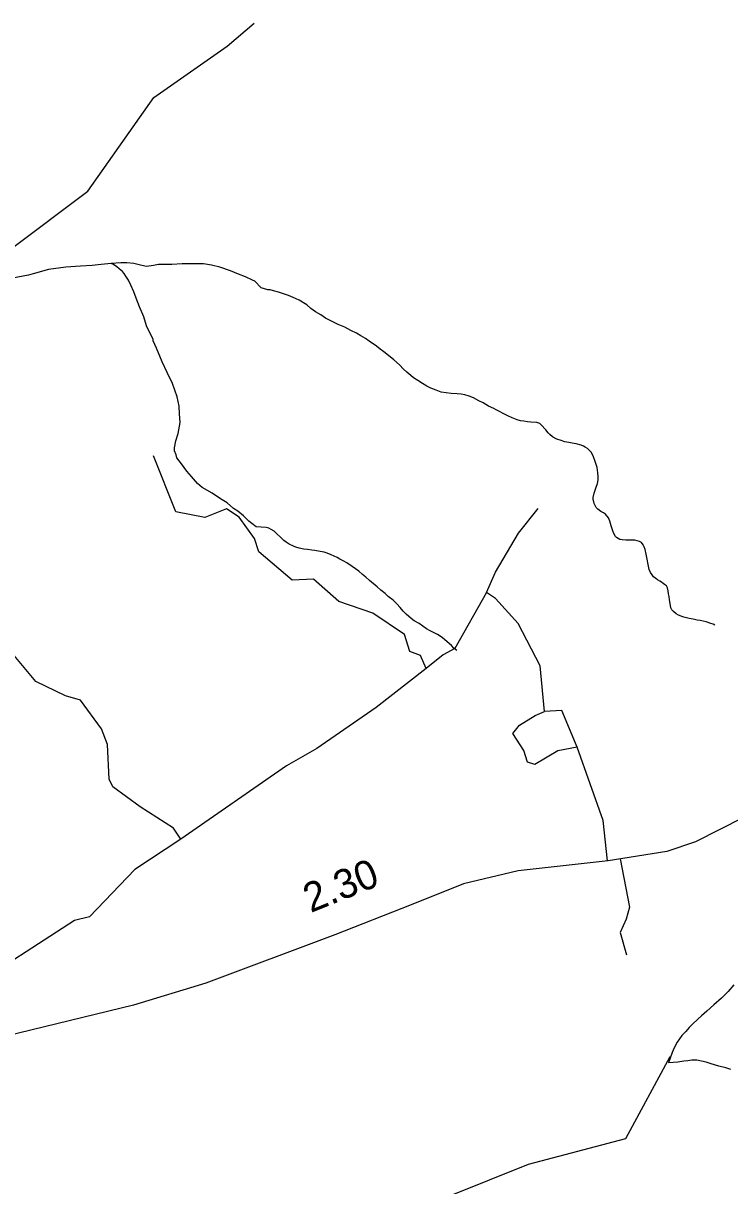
# Model space of a CAD drawing. Extents: x 2056842 to 2160602, y 826753 to 1016856.
# Drawn here: x 2109914 to 2112934, y 842001 to 846968 of the extents above; entities that cross this region are included whole.
import ezdxf

# ---------------------------------------------------------------- set-up
doc = ezdxf.new("R2010")
doc.units = 0
for name, color, linetype in [('Exist Hydrographic Creek Single Shore', 7, 'Continuous'), ('Exist Hydrographic Misc Water Feature', 7, 'Continuous'), ('Exist Road Non-System Type 51', 7, 'Continuous'), ('Exist Road Secondary Mileage Hundredths English Label', 7, 'Continuous'), ('Exist Road Secondary Type 51 Attributed', 7, 'Continuous')]:
    doc.layers.add(name, color=color, linetype=linetype)

msp = doc.modelspace()

# ---------------------------------------------------------------- linework, layer by layer
at = {"layer": 'Exist Hydrographic Creek Single Shore'}
msp.add_lwpolyline([(2108168.9, 845471), (2108304.5, 845502.1), (2109014.8, 845654.3), (2109225, 845779.8), (2109375, 845866), (2109549.9, 845924.8), (2109733, 845940.7), (2109857.9, 846000.5), (2110190.9, 846249.6), (2110472.9, 846650.6), (2110785.6, 846869.5), (2110900.7, 846967.7)], dxfattribs=at)
at = {"layer": 'Exist Hydrographic Misc Water Feature'}
for points in [[(2110290.4, 845940.5), (2110246.6, 845936.3), (2110208.8, 845932.2), (2110158.8, 845930.1), (2110096.5, 845925.7), (2110022.4, 845915.4), (2109956.6, 845897.4), (2109936.7, 845891.1), (2109868.9, 845879), (2109706.9, 845864.7), (2109641, 845852.3), (2109580.5, 845834.3), (2109519, 845829.7), (2109494.8, 845829.8), (2109443, 845821.8), (2109404.8, 845809.8), (2109363, 845795.4), (2109317.1, 845785.3), (2109225, 845779.8)], [(2110904.6, 845866.2), (2110894.5, 845870.1), (2110864.6, 845884), (2110834.6, 845896.2), (2110800.4, 845909.9), (2110754.3, 845925.9), (2110718.2, 845933.8), (2110684.3, 845939.7), (2110658.3, 845939.6), (2110594.1, 845939.2), (2110548.8, 845937.1), (2110518.5, 845936.8), (2110492.6, 845937.1), (2110470.3, 845932.8), (2110440.7, 845928.7), (2110420.4, 845932.6), (2110386.6, 845940.6), (2110356.7, 845944.7), (2110330.8, 845944.6), (2110290.4, 845940.5)], [(2110909.9, 844816.5), (2110891.9, 844830.6), (2110877.7, 844840.5), (2110856, 844862.4), (2110831.6, 844882.4), (2110813.5, 844894), (2110785.6, 844918.1), (2110757.8, 844936.1), (2110721.3, 844959.9), (2110679.4, 844983.7), (2110659.5, 845001.7), (2110633.5, 845031.7), (2110612.8, 845053.5), (2110591, 845085.6), (2110571, 845111.3), (2110567.1, 845123.3), (2110560.7, 845141.3), (2110561.1, 845153.4), (2110566.9, 845183.4), (2110576.5, 845215.2), (2110584.5, 845261.4), (2110582.4, 845299.5), (2110580.4, 845331.4), (2110571.8, 845371.2), (2110552.1, 845429), (2110529.5, 845475.1), (2110508, 845520.9), (2110483.6, 845579), (2110469.7, 845610.7), (2110469.5, 845616.8), (2110441.4, 845675), (2110428.9, 845712.6), (2110411.2, 845756.7), (2110396.9, 845792.6), (2110387, 845820.8), (2110374.7, 845848.7), (2110364.3, 845870.5), (2110352.6, 845886.5), (2110344.8, 845898.6), (2110338.8, 845906.4), (2110324.7, 845918.3), (2110314.4, 845926.3), (2110300.5, 845936.2), (2110290.4, 845940.5)], [(2111949.7, 845308.2), (2111935.6, 845315.6), (2111925.5, 845321.6), (2111903.4, 845331.9), (2111879.4, 845345.6), (2111861.3, 845354.8), (2111839.2, 845366.7), (2111820.9, 845374.8), (2111801.1, 845380.6), (2111785.3, 845382.6), (2111769.1, 845384.7), (2111742.8, 845386.2), (2111701, 845391.8), (2111678.8, 845399.5), (2111656.7, 845409), (2111638.9, 845417.7), (2111620.8, 845428.6), (2111600.7, 845440.6), (2111582.3, 845452.7), (2111570.8, 845462.6), (2111554.4, 845476.8), (2111540.2, 845490.3), (2111522, 845508.9), (2111497.8, 845529.6), (2111475.8, 845548.4), (2111455.5, 845563.6), (2111439.6, 845575.4), (2111423.4, 845588), (2111393.4, 845609.2), (2111377, 845621), (2111357.3, 845632.8), (2111339.1, 845642.9), (2111314.7, 845655.1), (2111288.4, 845668.5), (2111260.7, 845680.8), (2111232.4, 845694.4), (2111206.2, 845708.1), (2111186.5, 845721.6), (2111164, 845735.2), (2111143.9, 845749.6), (2111126, 845764.5), (2111093.8, 845785.2), (2111067.6, 845796.1), (2111047.5, 845804), (2111005.3, 845818.1), (2110983.3, 845824.2), (2110969.6, 845828), (2110959.5, 845829), (2110945.2, 845832.4), (2110931.6, 845837.3), (2110904.6, 845866.2)], [(2112871, 844395.7), (2112863.2, 844400.1), (2112853.2, 844403.7), (2112833.5, 844409.5), (2112807.2, 844415.1), (2112795.2, 844416.9), (2112777.5, 844420.8), (2112761.1, 844424.9), (2112743.1, 844428.9), (2112733, 844432), (2112715, 844438.4), (2112704.9, 844444.4), (2112693, 844454.3), (2112687.1, 844461.7), (2112682.8, 844469.3), (2112680.7, 844480.1), (2112676.6, 844503.9), (2112674.4, 844518), (2112672.1, 844530.1), (2112671.5, 844542.4), (2112667.8, 844555.9), (2112663.3, 844563.9), (2112655.7, 844569.9), (2112649.6, 844574.1), (2112641.8, 844580.2), (2112635.8, 844583.5), (2112625.8, 844589.5), (2112617.4, 844595.2), (2112608.6, 844603), (2112602.2, 844610.5), (2112594.8, 844620.5), (2112589.9, 844633.9), (2112585.4, 844655.3), (2112581.1, 844677.4), (2112576.6, 844699.6), (2112572.3, 844719.3), (2112568.6, 844730.8), (2112564.1, 844739.2), (2112556.5, 844749.3), (2112548.3, 844753.4), (2112538.2, 844756.9), (2112528.2, 844758.8), (2112518.5, 844759.1), (2112490.4, 844758.9), (2112474.2, 844760.9), (2112464.2, 844762.4), (2112450.3, 844770.2), (2112446.4, 844774.5), (2112438, 844787.5), (2112434.3, 844798.6), (2112429.5, 844811.9), (2112427.5, 844820), (2112421.5, 844839.9), (2112415.8, 844853.8), (2112403.1, 844869.5), (2112395.1, 844875.6), (2112383.4, 844881.4), (2112369.5, 844891.6), (2112362.9, 844899.1), (2112358.8, 844907.4), (2112355.1, 844915.7), (2112353.1, 844923.4), (2112350.8, 844933), (2112350.8, 844941.1), (2112354.3, 844959.2), (2112362.5, 844985.2), (2112368.2, 845001.8), (2112371.5, 845017.1), (2112372.1, 845030.4), (2112369.9, 845047.4), (2112367, 845068.9), (2112359, 845095.2), (2112351.8, 845115.8), (2112342.8, 845133.4), (2112326.6, 845150.9), (2112316.6, 845156.9), (2112309, 845161.3), (2112298.9, 845164.9), (2112277, 845171), (2112261, 845174.2), (2112246.8, 845176.4), (2112228.6, 845179.9), (2112212.8, 845184.3), (2112194.8, 845189.9), (2112176.3, 845200), (2112164.4, 845210), (2112158.5, 845217.8), (2112148.2, 845230.3), (2112128.5, 845251.9), (2112121.8, 845257.8), (2112110.1, 845261.2), (2112084, 845263.5), (2112069.9, 845265.2), (2112054.1, 845267.2), (2112039.9, 845268.6), (2112025.8, 845272.8), (2112003.9, 845282.2), (2111985.8, 845290.2), (2111965.7, 845300.1), (2111949.7, 845308.2)], [(2111767, 844288.3), (2111754.7, 844298.3), (2111744.9, 844308.3), (2111736.3, 844315.6), (2111724.4, 844325.9), (2111716.4, 844333.3), (2111706.7, 844342), (2111696.5, 844349.3), (2111684.4, 844355.6), (2111670.2, 844363), (2111653.8, 844371.5), (2111638, 844380.8), (2111622, 844392.2), (2111606.1, 844403.1), (2111585.8, 844414.7), (2111571.6, 844424.2), (2111551.3, 844442.6), (2111538.6, 844455.9), (2111525.7, 844471.7), (2111511.3, 844487.7), (2111494.9, 844502.3), (2111474.6, 844518), (2111460.7, 844531.4), (2111442.8, 844545.9), (2111426.6, 844559.3), (2111394.4, 844586.9), (2111378, 844601.2), (2111364.3, 844613), (2111348.3, 844626.4), (2111319.8, 844646.9), (2111297.7, 844662), (2111281.7, 844670.5), (2111267.7, 844678.3), (2111255.4, 844684.3), (2111229.8, 844696.3), (2111213.6, 844703.2), (2111201.1, 844707.5), (2111183.4, 844711), (2111161.1, 844714.8), (2111147.4, 844716.8), (2111129.5, 844718.8), (2111113.3, 844720.8), (2111093.6, 844725), (2111079.3, 844729.2), (2111069.4, 844733.9), (2111051.4, 844742.4), (2111037.9, 844750.9), (2111027.6, 844758.1), (2111017.8, 844767.7), (2110993.6, 844790.8), (2110986.2, 844796.8), (2110973.9, 844805.2), (2110964.2, 844810.7), (2110952.3, 844813.4), (2110909.9, 844816.5)], [(2112951.6, 842858.7), (2112927.8, 842830.3), (2112898.1, 842802.3), (2112866.5, 842773.4), (2112836.6, 842747.1)], [(2112836.6, 842747.1), (2112812.8, 842726.8), (2112798.6, 842713.5), (2112773, 842689.4), (2112761.1, 842676.6), (2112745.7, 842660.3), (2112729.5, 842642.4), (2112709.8, 842614.2), (2112696.1, 842589.9), (2112688.1, 842570.4), (2112672.7, 842525.7)], [(2110926, 841729.7), (2111299.8, 841899.1), (2111740.9, 841958.9), (2112073.9, 842093.2), (2112489.9, 842202.7), (2112679.8, 842553.2)], [(2112938.7, 842498), (2112916.7, 842504.1), (2112886.8, 842512.3), (2112854.8, 842522), (2112833.5, 842528.9), (2112812.6, 842533.3), (2112792.7, 842537.1), (2112771.8, 842536.6), (2112754.6, 842534.4), (2112738.4, 842532.4), (2112711.9, 842529.1), (2112672.7, 842525.7)]]:
    msp.add_lwpolyline(points, dxfattribs=at)
at = {"layer": 'Exist Road Non-System Type 51'}
for points in [[(2111636, 844210.9), (2111612.1, 844266), (2111566.4, 844282.7), (2111543.6, 844355.4), (2111408.6, 844446.9), (2111263.2, 844496.7), (2111155.2, 844592.3), (2111063.8, 844588.2), (2110921.5, 844709.8), (2110902.8, 844765.9), (2110836.4, 844857.3), (2110782.4, 844892.7), (2110691, 844855.3), (2110566.4, 844880.2), (2110470.8, 845119.2)], [(2111893.6, 844535.2), (2111933, 844622.5), (2112030.7, 844788.8), (2112115.8, 844894.8)], [(2111893.6, 844535.2), (2111758.6, 844296.2), (2111708.7, 844269.1), (2111636, 844210.9)], [(2112141.8, 844027), (2112123.1, 844222.4), (2112029.6, 844403.2), (2111933, 844510.2), (2111893.6, 844535.2)], [(2110587.1, 843481.4), (2110557, 843528.2), (2110413.7, 843619.6), (2110297.4, 843704.8), (2110280.8, 843738.1), (2110274.5, 843885.7), (2110248.6, 843953.2), (2110159.3, 844075.8), (2110094.9, 844094.6), (2109968.2, 844154.8), (2109833.2, 844316.9)], [(2111636, 844210.9), (2111423.1, 844043.6), (2111169.7, 843869), (2111038.9, 843794.2), (2110587.1, 843481.4)], [(2112282, 843874.2), (2112199.9, 843858.6), (2112100.2, 843800.5), (2112069.1, 843810.8), (2112054.5, 843860.7), (2112006.8, 843933.5), (2112035.8, 843968.8), (2112102.3, 844010.4), (2112141.8, 844027)], [(2112282, 843874.2), (2112216.5, 844031.2), (2112141.8, 844027)], [(2112410.8, 843388.9), (2112393.1, 843561.4), (2112282, 843874.2)], [(2110587.1, 843481.4), (2110390.9, 843351.5), (2110197.7, 843149.9), (2110133.3, 843133.3), (2109199.7, 842529.5)], [(2112465.2, 843397.4), (2112505.2, 843191.5), (2112490.7, 843139.5), (2112465.8, 843083.4), (2112492.8, 842987.8)]]:
    msp.add_lwpolyline(points, dxfattribs=at)
at = {"layer": 'Exist Road Secondary Type 51 Attributed'}
msp.add_lwpolyline([(2116388.1, 843944.1), (2116249.6, 844047.3), (2116106.3, 844132.5), (2115956.7, 844194.8), (2115805.1, 844242.6), (2115715.8, 844263.4), (2115574.5, 844278), (2115274.4, 844283.2), (2114738.6, 844291.5), (2114514.2, 844283.2), (2114303.4, 844238.5), (2114074.9, 844157.4), (2113740.5, 843968.3), (2113399.9, 843781.2), (2112788.2, 843470.5), (2112665.7, 843428.9), (2112414.4, 843389.4), (2112030.1, 843345.8), (2111796.5, 843290.7), (2111572.2, 843201.3), (2111246.1, 843072.5), (2110694.6, 842865.7), (2110385.1, 842772.1), (2109841, 842639.1)], dxfattribs=at)

# ---------------------------------------------------------------- texts
at = {"layer": 'Exist Road Secondary Mileage Hundredths English Label'}
msp.add_text('2.30', height=125, rotation=21.8642, dxfattribs=at).set_placement((2111142.6, 843165.7))

doc.saveas('drawing.dxf')
